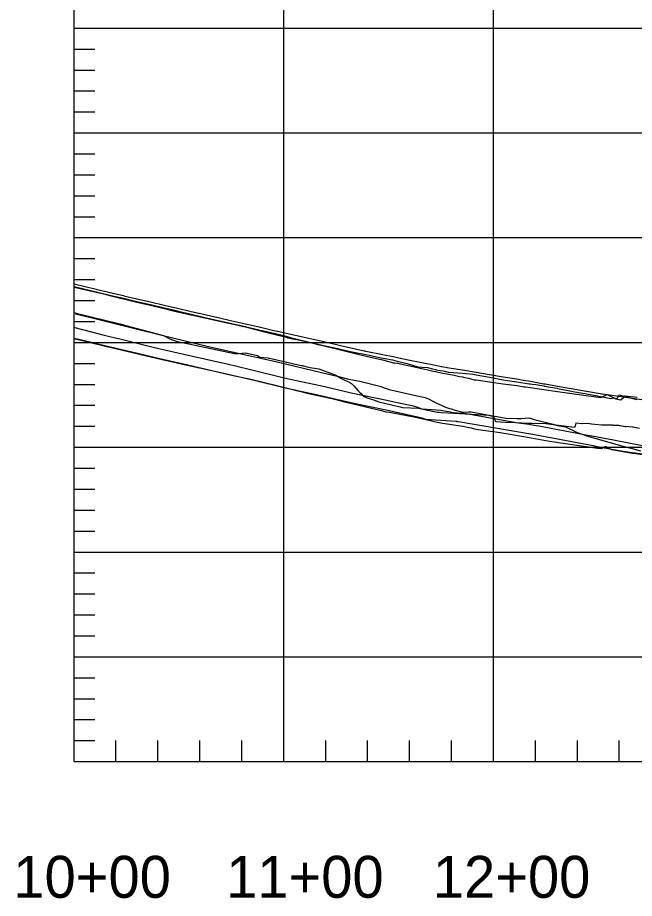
# Model space of a CAD drawing. Extents: x 704797 to 712284, y 374940 to 376945.
# Drawn here: x 708106.8 to 708400.9, y 375160.2 to 375580.5 of the extents above; entities that cross this region are included whole.
import ezdxf

# ---------------------------------------------------------------- set-up
doc = ezdxf.new("R2010")
doc.units = 0
for name, color, linetype in [('10', 7, 'Continuous'), ('12', 7, 'Continuous'), ('13', 7, 'Continuous'), ('61', 7, 'Continuous'), ('63', 7, 'Continuous'), ('Existing', 7, 'Continuous')]:
    doc.layers.add(name, color=color, linetype=linetype)

msp = doc.modelspace()

# ---------------------------------------------------------------- linework, layer by layer
at = {"layer": '10'}
for points in [[(708133.69, 375439.73), (708134.76, 375439.47), (708155.61, 375434.31), (708155.61, 375434.31), (708155.66, 375434.3), (708155.98, 375434.22), (708176.28, 375428.84), (708179.34, 375427.13), (708182.39, 375426.07), (708210.14, 375420.26), (708212.04, 375420.15), (708215.59, 375420.47), (708216.24, 375420.32), (708221.15, 375419.28), (708222.3, 375418.47), (708226.34, 375418.16), (708241.94, 375414.47), (708242.59, 375414.52), (708244.15, 375414), (708246.24, 375413.5), (708249.33, 375413.04), (708250.42, 375412.8), (708258.47, 375409.87), (708259.35, 375409.33), (708260.9, 375408.42), (708262.5, 375407.6), (708264.18, 375406.83), (708265, 375406.52), (708265.94, 375405.83), (708265.94, 375405.82), (708266.94, 375404.86), (708267.07, 375404.74), (708268.06, 375403.67), (708268.24, 375403.5), (708269.22, 375402.41), (708269.93, 375401.6), (708270.55, 375401.03), (708271.12, 375400.42), (708272.09, 375399.6), (708272.69, 375399.44), (708273.08, 375399.27), (708273.51, 375399.08), (708276.41, 375398.04), (708279.06, 375397.06), (708290.46, 375394.38), (708297.87, 375394.05), (708306.84, 375392.26), (708307.08, 375392.18), (708307.81, 375392.17), (708308.97, 375391.99), (708331.72, 375390.71), (708339.62, 375389.37), (708339.71, 375389.36), (708344.75, 375389.22), (708346.96, 375389.15), (708350.63, 375389.48), (708353.13, 375388.72), (708362.08, 375386.4), (708362.97, 375386.23), (708363.62, 375385.96), (708364.13, 375385.85), (708365.14, 375385.7), (708366.17, 375385.46), (708367.97, 375385.13), (708373.67, 375382.49), (708379.22, 375380.66), (708382.55, 375379.59), (708394.93, 375376.12), (708399.74, 375374.83), (708403.87, 375373.68)], [(708403.38, 375384.42), (708400.09, 375384.97), (708400, 375384.99), (708399.76, 375385.03), (708396.81, 375385.31), (708396.58, 375385.14), (708396.43, 375385.14), (708394.07, 375385.69), (708393.71, 375385.72), (708393.44, 375385.76), (708390.68, 375385.91), (708390.55, 375385.93), (708390.46, 375385.95), (708389.51, 375386.03), (708389.13, 375386.03), (708387.57, 375386.05), (708387.45, 375386.05), (708385.39, 375386.05), (708381.97, 375386.37), (708380.38, 375386.55), (708379.49, 375386.63), (708378.62, 375386.78), (708376.1, 375386.6), (708375.92, 375386.6), (708372.99, 375386.96), (708372.65, 375385.69), (708372.38, 375384.87), (708362.14, 375386.21), (708358.85, 375386.64), (708352.06, 375386.79), (708351.39, 375386.77), (708350.46, 375386.78), (708349.16, 375386.82), (708347.25, 375386.89), (708344.31, 375387.03), (708339.31, 375387.29), (708334.89, 375387.52), (708334.62, 375388.13), (708334.28, 375388.77), (708333.82, 375390.04), (708330.06, 375390.91), (708324.8, 375391.95), (708322.97, 375392.16), (708322.11, 375392.14), (708321.78, 375392.13), (708319.48, 375391.97), (708318.95, 375392.08), (708318.43, 375392.25), (708316.24, 375392.79), (708315.64, 375393), (708313.61, 375393.57), (708312.96, 375393.83), (708310.97, 375394.47), (708310.31, 375394.74), (708308.26, 375395.63), (708305.98, 375396.73), (708303.19, 375398.21), (708301.32, 375399.02), (708298.67, 375399.56), (708284.03, 375402.92), (708283.25, 375403.16), (708282.26, 375403.52), (708280.09, 375404.24), (708270, 375406.78), (708268.14, 375407.19), (708264.91, 375407.85), (708260.58, 375408.88), (708251.7, 375411.01), (708230.55, 375416.13), (708208.39, 375421.03), (708205.55, 375421.7), (708197.84, 375423.44), (708175.57, 375428.71), (708163.96, 375431.67), (708142.32, 375437.07), (708134.39, 375438.99)]]:
    msp.add_lwpolyline(points, dxfattribs=at)
at = {"layer": '12'}
for points in [[(708133.69, 375432.68), (708134.02, 375432.59), (708148.08, 375428.91), (708156.15, 375426.96), (708172.11, 375423.11), (708183.26, 375420.44), (708202.2, 375416.19), (708206.78, 375415.19), (708217.25, 375412.76), (708234.55, 375408.41), (708253.22, 375404.37), (708265.87, 375401.49), (708282.9, 375398), (708284.83, 375397.5), (708295.34, 375395.24), (708297.44, 375394.55), (708299.44, 375393.84), (708299.66, 375393.82), (708308.6, 375393.21), (708310.14, 375392.84), (708311.33, 375392.61), (708312.34, 375392.45), (708313.2, 375392.31), (708313.91, 375392.18), (708314.5, 375392.04), (708320.64, 375391.6), (708345.42, 375387.16), (708350.63, 375386.4), (708351.32, 375386.31), (708352.13, 375386.2), (708353.08, 375386.06), (708354.17, 375385.88), (708355.47, 375385.66), (708356.95, 375385.39), (708358.65, 375385.07), (708376.14, 375381.72), (708377.68, 375381.44), (708379.84, 375381.03), (708390.95, 375378.92), (708404.72, 375376.29)], [(708133.69, 375427.41), (708148.65, 375423.72), (708156.15, 375421.96), (708170.91, 375418.5), (708184.72, 375415.29), (708203.76, 375411.15), (708220.29, 375407.32), (708233.71, 375403.95), (708248.56, 375400.73), (708267.15, 375396.49), (708280.97, 375393.65), (708282.56, 375393.24), (708296.05, 375390.33), (708297.61, 375390.02), (708299.55, 375389.44), (708301.32, 375388.87), (708315.75, 375387.9), (708316.05, 375387.84), (708316.28, 375387.79), (708316.47, 375387.77), (708316.63, 375387.74), (708316.76, 375387.72), (708316.86, 375387.7), (708317.91, 375387.63), (708350.44, 375382.01), (708350.52, 375382), (708350.53, 375382), (708350.54, 375382), (708350.56, 375382), (708350.57, 375381.99), (708350.59, 375381.99), (708350.61, 375381.99), (708350.63, 375381.98), (708381.27, 375376.22), (708382.41, 375376), (708388.27, 375374.9), (708395.49, 375373.52), (708422.66, 375369.78)]]:
    msp.add_lwpolyline(points, dxfattribs=at)
at = {"layer": '13'}
msp.add_lwpolyline([(708408.28, 375371.35), (708399.09, 375372.68), (708390.07, 375374.27), (708387.12, 375375.77), (708384.97, 375374.75), (708383.3, 375374.92), (708360.4, 375378.22), (708348.14, 375380.39), (708336.94, 375382.32), (708327.72, 375383.68), (708325.46, 375383.96), (708324.88, 375384.12), (708324.14, 375384.29), (708323.14, 375384.49), (708321.9, 375384.74), (708320.54, 375385), (708319.16, 375385.28), (708309.37, 375386.78), (708307.81, 375387.13), (708306.15, 375387.49), (708304.36, 375387.88), (708296.49, 375389.61), (708284.04, 375392.04), (708282.49, 375392.22), (708280.87, 375392.65), (708263.53, 375396.86), (708258.09, 375398.21), (708245.51, 375400.97), (708242.67, 375401.7), (708240.48, 375402.26), (708235.54, 375403.53), (708230.43, 375404.8), (708218.65, 375407.56), (708208.21, 375409.9), (708196.14, 375412.65), (708185.25, 375415.24), (708175.23, 375417.54), (708164.63, 375420.1), (708153.21, 375422.78), (708145.66, 375424.55), (708142.6, 375425.27), (708133.88, 375427.31)], dxfattribs=at)
at = {"layer": '61'}
for p, q in [((708133.69, 375225.47), (708133.69, 375925.47)), ((708233.69, 375225.47), (708233.69, 375925.47)), ((708333.69, 375225.47), (708333.69, 375925.47)), ((708133.69, 375575.47), (712133.69, 375575.47)), ((708133.69, 375565.47), (708143.69, 375565.47)), ((708133.69, 375555.47), (708143.69, 375555.47)), ((708133.69, 375545.47), (708143.69, 375545.47)), ((708133.69, 375535.47), (708143.69, 375535.47)), ((708133.69, 375525.47), (712133.69, 375525.47)), ((708133.69, 375515.47), (708143.69, 375515.47)), ((708133.69, 375505.47), (708143.69, 375505.47)), ((708133.69, 375495.47), (708143.69, 375495.47)), ((708133.69, 375485.47), (708143.69, 375485.47)), ((708133.69, 375475.47), (712133.69, 375475.47)), ((708133.69, 375465.47), (708143.69, 375465.47)), ((708133.69, 375455.47), (708143.69, 375455.47)), ((708133.69, 375445.47), (708143.69, 375445.47)), ((708133.69, 375435.47), (708143.69, 375435.47)), ((708133.69, 375425.47), (712133.69, 375425.47)), ((708133.69, 375415.47), (708143.69, 375415.47)), ((708133.69, 375405.47), (708143.69, 375405.47)), ((708133.69, 375395.47), (708143.69, 375395.47)), ((708133.69, 375385.47), (708143.69, 375385.47)), ((708133.69, 375375.47), (712133.69, 375375.47)), ((708133.69, 375365.47), (708143.69, 375365.47)), ((708133.69, 375355.47), (708143.69, 375355.47)), ((708133.69, 375345.47), (708143.69, 375345.47)), ((708133.69, 375335.47), (708143.69, 375335.47)), ((708133.69, 375325.47), (712133.69, 375325.47)), ((708133.69, 375315.47), (708143.69, 375315.47)), ((708133.69, 375305.47), (708143.69, 375305.47)), ((708133.69, 375295.47), (708143.69, 375295.47)), ((708133.69, 375285.47), (708143.69, 375285.47)), ((708133.69, 375275.47), (712133.69, 375275.47)), ((708133.69, 375265.47), (708143.69, 375265.47)), ((708133.69, 375255.47), (708143.69, 375255.47)), ((708133.69, 375245.47), (708143.69, 375245.47)), ((708133.69, 375235.47), (708143.69, 375235.47)), ((708153.69, 375225.47), (708153.69, 375235.47)), ((708173.69, 375225.47), (708173.69, 375235.47)), ((708193.69, 375225.47), (708193.69, 375235.47)), ((708213.69, 375225.47), (708213.69, 375235.47)), ((708253.69, 375225.47), (708253.69, 375235.47)), ((708273.69, 375225.47), (708273.69, 375235.47)), ((708293.69, 375225.47), (708293.69, 375235.47)), ((708313.69, 375225.47), (708313.69, 375235.47)), ((708353.69, 375225.47), (708353.69, 375235.47)), ((708373.69, 375225.47), (708373.69, 375235.47)), ((708393.69, 375225.47), (708393.69, 375235.47)), ((708133.69, 375225.47), (712133.69, 375225.47))]:
    msp.add_line(p, q, dxfattribs=at)
at = {"layer": '63'}
for points in [[(708133.69, 375452.18), (708144.27, 375449.55), (708150.74, 375447.9), (708153.24, 375447.26), (708155.7, 375446.66), (708157.21, 375446.3), (708163.67, 375444.74), (708170.14, 375443.19), (708176.61, 375441.63), (708176.76, 375441.6), (708180.39, 375440.73), (708183.08, 375440.13), (708189.55, 375438.7), (708196.02, 375437.26), (708202.49, 375435.83), (708208.96, 375434.39), (708209.87, 375434.19), (708213.87, 375433.25), (708215.43, 375432.85), (708221.9, 375431.21), (708228.37, 375429.56), (708234.84, 375427.92), (708235.63, 375427.72), (708241.31, 375426.48), (708247.77, 375425.07), (708254.24, 375423.66), (708259.5, 375422.53), (708260.71, 375422.25), (708264.06, 375421.49), (708267.18, 375420.84), (708273.65, 375419.52), (708280.12, 375418.2), (708285.47, 375417.11), (708286.59, 375416.82), (708287.83, 375416.5), (708292.54, 375415.5), (708293.06, 375415.33), (708295.15, 375414.66), (708297.6, 375413.81), (708299.53, 375413.67), (708302.18, 375413.48), (708304.62, 375412.84), (708306, 375412.55), (708306.57, 375412.43), (708308.28, 375412.13), (708309.75, 375411.87), (708310.99, 375411.62), (708312.05, 375411.34), (708312.47, 375411.31), (708318.94, 375410.78), (708323.83, 375410.39), (708325.41, 375410.09), (708331.87, 375408.89), (708338.34, 375407.69), (708340.4, 375407.31), (708344.81, 375406.64), (708350.73, 375405.75), (708351.28, 375405.68), (708352.15, 375405.57), (708353.82, 375405.33), (708355.78, 375405.04), (708357.75, 375404.71), (708358.04, 375404.66), (708360.76, 375404.19), (708363.89, 375403.61), (708364.22, 375403.54), (708367.56, 375402.92), (708374.31, 375401.63), (708377.37, 375401.05), (708389.63, 375398.68), (708390.93, 375399.01), (708392.7, 375398.56), (708393.42, 375400.42), (708402.1, 375398.3)], [(708133.69, 375451.89), (708144.27, 375449.51), (708149.44, 375448.37), (708150.74, 375448.07), (708152, 375447.78), (708157.21, 375446.57), (708163.67, 375445.07), (708166.53, 375444.41), (708170.14, 375443.54), (708176.61, 375442), (708179.63, 375441.27), (708183.08, 375440.49), (708183.38, 375440.42), (708189.55, 375438.96), (708196.02, 375437.43), (708196.8, 375437.25), (708202.49, 375435.95), (708208.96, 375434.48), (708211.72, 375433.85), (708215.43, 375433.02), (708215.71, 375432.96), (708221.9, 375431.52), (708228.37, 375430), (708230.36, 375429.53), (708234.84, 375428.42), (708236.88, 375427.9), (708241.31, 375426.77), (708243.33, 375426.24), (708247.77, 375425.11), (708249.93, 375424.55), (708253.78, 375423.71), (708254.24, 375423.6), (708260.71, 375421.99), (708260.81, 375421.96), (708267.18, 375420.42), (708273.65, 375418.84), (708280.12, 375417.27), (708283.72, 375416.39), (708285.93, 375415.8), (708286.59, 375415.72), (708288.07, 375415.53), (708291.45, 375414.86), (708293.06, 375414.5), (708299.53, 375413.05), (708302.37, 375412.41), (708304.93, 375411.84), (708306, 375411.59), (708307.31, 375411.3), (708309.59, 375410.78), (708312.38, 375410.34), (708312.47, 375410.32), (708314.94, 375409.8), (708317.53, 375409.26), (708318.94, 375408.98), (708319.92, 375408.78), (708321.9, 375408.35), (708323.38, 375408), (708324.54, 375407.67), (708325.41, 375407.55), (708331.87, 375406.66), (708338.34, 375405.76), (708344.81, 375404.85), (708347.53, 375404.47), (708348.19, 375404.36), (708348.98, 375404.22), (708351.28, 375403.9), (708357.75, 375403), (708364.22, 375402.1), (708382.49, 375399.49), (708384.85, 375399.25), (708387.85, 375400.68), (708391.96, 375398.59), (708394.38, 375398.16), (708395.75, 375399.24), (708396.31, 375399.96), (708402.19, 375399.38)]]:
    msp.add_lwpolyline(points, dxfattribs=at)
at = {"layer": 'Existing'}
msp.add_lwpolyline([(708133.69, 375453.38), (708144.27, 375450.89), (708150.74, 375449.36), (708157.21, 375447.83), (708157.39, 375447.79), (708157.44, 375447.77), (708157.48, 375447.76), (708163.67, 375446.32), (708170.13, 375444.82), (708170.14, 375444.82), (708170.17, 375444.81), (708176.61, 375443.31), (708183.08, 375441.8), (708189.55, 375440.29), (708193.14, 375439.45), (708193.28, 375439.42), (708193.43, 375439.38), (708196.02, 375438.79), (708202.49, 375437.31), (708208.96, 375435.83), (708215.43, 375434.34), (708221.9, 375432.85), (708228.37, 375431.36), (708230.52, 375430.87), (708230.67, 375430.83), (708230.74, 375430.81), (708230.81, 375430.8), (708230.87, 375430.78), (708234.84, 375429.89), (708241.31, 375428.45), (708247.77, 375427), (708254.24, 375425.55), (708260.71, 375424.09), (708267.18, 375422.64), (708272.08, 375421.53), (708272.22, 375421.49), (708272.66, 375421.38), (708272.7, 375421.37), (708272.74, 375421.37), (708273.65, 375421.18), (708280.12, 375419.88), (708286.59, 375418.56), (708288.61, 375418.15), (708293.06, 375417.23), (708299.53, 375415.89), (708306, 375414.55), (708308.7, 375413.99), (708308.73, 375413.98), (708308.76, 375413.97), (708309.05, 375413.95), (708312.47, 375413.39), (708318.94, 375412.32), (708325.41, 375411.24), (708331.87, 375410.17), (708338.34, 375409.1), (708344.81, 375408.03), (708347.85, 375407.52), (708348.05, 375407.49), (708351.28, 375406.92), (708357.75, 375405.79), (708358.29, 375405.7), (708364.22, 375404.65), (708384.6, 375401.04), (708385.24, 375400.95), (708385.28, 375400.95), (708385.34, 375400.97), (708385.42, 375400.93), (708385.66, 375400.89), (708428.69, 375394.74)], dxfattribs=at)

# ---------------------------------------------------------------- texts
at = {"layer": '61'}
for s, p in [('10+00', (708104.77, 375160.47)), ('11+00', (708206.21, 375160.47)), ('12+00', (708304.77, 375160.47))]:
    msp.add_text(s, height=20, dxfattribs=at).set_placement(p)

doc.saveas('drawing.dxf')
